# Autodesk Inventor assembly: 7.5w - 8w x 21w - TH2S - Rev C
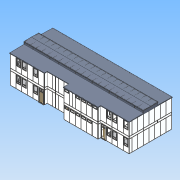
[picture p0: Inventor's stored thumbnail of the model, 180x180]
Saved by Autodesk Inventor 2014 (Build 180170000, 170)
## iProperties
Created: 2013-05
Part Number: 7.5w - 8w x 21w - TH2S - Rev C
Document SubType Name: Assembly
Designer: david.appleford
Mass: 5.25812e+07 g
Surface Area: 6.12104e+07 cm^2
Volume: 1.47344e+08 cm^3
Density: 0.356859 g/cm^3
Description: Coppice School Building
Justset: False
Title: Coppice School Building
Author: david.appleford
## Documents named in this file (76)
- C:\Documents and Settings\john.everitt\Local Settings\My Documents\Vault\Production MkII\4.00 BUILDINGS\Chigwell School\7.5w - 8w x 21w - TH2S - Rev C.iam
- C:\Documents and Settings\john.everitt\Local Settings\My Documents\Vault\Production MkII\VIRTUAL ELEMENTS\Virtual Walls\Virtual Timber + MgO\P0410S01K7L7-V.iam
- C:\Documents and Settings\john.everitt\Local Settings\My Documents\Vault\Production MkII\VIRTUAL ELEMENTS\Virtual Walls\Virtual Timber + MgO\P0409S01K7L6.5-V.iam
- C:\Documents and Settings\john.everitt\Local Settings\My Documents\Vault\Production MkII\VIRTUAL ELEMENTS\Virtual Walls\Virtual Timber + MgO\P0412S01K8L8-V.iam
- C:\Documents and Settings\john.everitt\Local Settings\My Documents\Vault\Production MkII\VIRTUAL ELEMENTS\Virtual Walls\Virtual Timber + MgO\P0408S01K6L6-V.iam
- C:\Documents and Settings\john.everitt\Local Settings\My Documents\Vault\Production MkII\VIRTUAL ELEMENTS\Virtual Walls\Virtual Timber + MgO\P0208S01K5L5-V.iam
- C:\Documents and Settings\john.everitt\Local Settings\My Documents\Vault\Production MkII\VIRTUAL ELEMENTS\Virtual Walls\Virtual Timber + MgO\P0204S01K3L3-V.iam
- C:\Documents and Settings\john.everitt\Local Settings\My Documents\Vault\Production MkII\VIRTUAL ELEMENTS\Virtual Walls\Virtual Timber + MgO\P0209S01K7L5.5L-V.iam
- C:\Documents and Settings\john.everitt\Local Settings\My Documents\Vault\Production MkII\VIRTUAL ELEMENTS\Virtual Walls\Virtual Timber + MgO\P0209S01K7L5.5R-V.iam
- C:\Documents and Settings\john.everitt\Local Settings\My Documents\Vault\Production MkII\VIRTUAL ELEMENTS\Virtual Walls\Virtual Timber + MgO\P0409S01K7L4.5-V.iam
- C:\Documents and Settings\john.everitt\Local Settings\My Documents\Vault\Production MkII\VIRTUAL ELEMENTS\Virtual Walls\Virtual Timber + MgO\P0409S01K7L2.5-V.iam
- C:\Documents and Settings\john.everitt\Local Settings\My Documents\Vault\Production MkII\VIRTUAL ELEMENTS\Virtual Walls\Virtual Timber + MgO\P0409S01K7L2-V.iam
- C:\Documents and Settings\john.everitt\Local Settings\My Documents\Vault\Production MkII\VIRTUAL ELEMENTS\Virtual Walls\Virtual Timber + MgO\P0209S01K7L4.5-V.iam
- C:\Documents and Settings\john.everitt\Local Settings\My Documents\Vault\Production MkII\VIRTUAL ELEMENTS\Virtual Walls\Virtual Timber + MgO\P0209S01K7L2.5-V.iam
- C:\Documents and Settings\john.everitt\Local Settings\My Documents\Vault\Production MkII\Virtual Elements\Virtual Walls\Virtual Timber + MgO\P0409S01K7-V.ipt
- C:\Documents and Settings\john.everitt\Local Settings\My Documents\Vault\Production MkII\4.00 BUILDINGS\Chigwell School\Stairs RH - U18R - 2.25w + 400mm Joist .ipt
- C:\Documents and Settings\john.everitt\Local Settings\My Documents\Vault\Production MkII\VIRTUAL ELEMENTS\Virtual Walls\Virtual Timber + MgO\P0406S01K5L2-V.iam
- C:\Documents and Settings\john.everitt\Local Settings\My Documents\Vault\Production MkII\VIRTUAL ELEMENTS\Virtual Ceilings\Ceiling MgO & Timber Frame\P0410C02K7L7-V.iam
- C:\Documents and Settings\john.everitt\Local Settings\My Documents\Vault\Production MkII\VIRTUAL ELEMENTS\Virtual Ceilings\Ceiling MgO & Timber Frame\P0412C02K8L8-V.iam
- C:\Documents and Settings\john.everitt\Local Settings\My Documents\Vault\Production MkII\VIRTUAL ELEMENTS\Virtual Ceilings\Ceiling MgO & Timber Frame\P0408C02K6L6-V.iam
- C:\Documents and Settings\john.everitt\Local Settings\My Documents\Vault\Production MkII\VIRTUAL ELEMENTS\Virtual Ceilings\Ceiling MgO & Timber Frame\P0204C02K3L3-V.iam
- C:\Documents and Settings\john.everitt\Local Settings\My Documents\Vault\Production MkII\VIRTUAL ELEMENTS\Virtual Joists\J16H397K18-T-V.ipt
- C:\Documents and Settings\john.everitt\Local Settings\My Documents\Vault\Production MkII\Virtual Elements\Virtual Joists\J14H400K16-T-V.ipt
- C:\Documents and Settings\john.everitt\Local Settings\My Documents\Vault\Production MkII\VIRTUAL ELEMENTS\Virtual Joists\J20H397K22-T-V.ipt
- C:\Documents and Settings\john.everitt\Local Settings\My Documents\Vault\Production MkII\Virtual Elements\Virtual Joists\J12S400K14-V.ipt
- C:\Documents and Settings\john.everitt\Local Settings\My Documents\Vault\Production MkII\Virtual Elements\Virtual Joists\J10S400K12-V.ipt
- C:\Documents and Settings\john.everitt\Local Settings\My Documents\Vault\Production MkII\Virtual Elements\Virtual Joists\J08S400K14-V.ipt
- C:\Documents and Settings\john.everitt\Local Settings\My Documents\Vault\Production MkII\VIRTUAL ELEMENTS\Virtual Joists\J04S397K5-V.ipt
- C:\Documents and Settings\john.everitt\Local Settings\My Documents\Vault\Production MkII\VIRTUAL ELEMENTS\Virtual Joists\J06S400K08-V.ipt
- C:\Documents and Settings\john.everitt\Local Settings\My Documents\Vault\Production MkII\Virtual Elements\Virtual Joists\J02S400K4-V.ipt
- C:\Documents and Settings\john.everitt\Local Settings\My Documents\Vault\Production MkII\VIRTUAL ELEMENTS\Virtual Lugs\Superceded Lugs\L400J3-V.ipt
- C:\Documents and Settings\john.everitt\Local Settings\My Documents\Vault\Production MkII\VIRTUAL ELEMENTS\Virtual Walls\Virtual Timber + MgO\P0409S01K7L5.5T-V.iam
- C:\Documents and Settings\john.everitt\Local Settings\My Documents\Vault\Production MkII\VIRTUAL ELEMENTS\Virtual Walls\Virtual Timber + MgO\P0409S01K7L3T-V.iam
- C:\Documents and Settings\john.everitt\Local Settings\My Documents\Vault\Production MkII\VIRTUAL ELEMENTS\Virtual Walls\Virtual Timber + MgO\P0409S01K7L3.5T-V.iam
- C:\Documents and Settings\john.everitt\Local Settings\My Documents\Vault\Production MkII\VIRTUAL ELEMENTS\Virtual Lugs\Superceded Lugs\LA02C3V.ipt
- C:\Documents and Settings\john.everitt\Local Settings\My Documents\Vault\Production MkII\VIRTUAL ELEMENTS\Virtual Lugs\Superceded Lugs\LA02M3V.ipt
- C:\Documents and Settings\john.everitt\Local Settings\My Documents\Vault\Production MkII\Virtual Elements\Virtual Walls\Virtual Timber + MgO\P0404S01K4L4-V.iam
- C:\Documents and Settings\john.everitt\Local Settings\My Documents\Vault\Production MkII\VIRTUAL ELEMENTS\Virtual Ceilings\Ceiling MgO & Timber Frame\P0212C02K8L7-V.iam
- C:\Documents and Settings\john.everitt\Local Settings\My Documents\Vault\Production MkII\VIRTUAL ELEMENTS\Virtual Ceilings\Ceiling MgO & Timber Frame\P0208C02K5L5-V.iam
- C:\Documents and Settings\john.everitt\Local Settings\My Documents\Vault\Production MkII\VIRTUAL ELEMENTS\Virtual Walls\Virtual Timber + MgO\P0404S01K4L1-V.iam
- C:\Documents and Settings\john.everitt\Local Settings\My Documents\Vault\Production MkII\VIRTUAL ELEMENTS\Virtual Walls\Virtual Timber + MgO\P0212S01K8L7-V.iam
- C:\Documents and Settings\john.everitt\Local Settings\My Documents\Vault\Production MkII\VIRTUAL ELEMENTS\Virtual Walls\Virtual Timber + MgO\P0206S01K5L4L-V.iam
- C:\Documents and Settings\john.everitt\Local Settings\My Documents\Vault\Production MkII\VIRTUAL ELEMENTS\Virtual Walls\Virtual Timber + MgO\P0206S01K5L4R-V.iam
- C:\Documents and Settings\john.everitt\Local Settings\My Documents\Vault\Production MkII\VIRTUAL ELEMENTS\Virtual Walls\Virtual Timber + MgO\P0212S01K8L4L-V.iam
- C:\Documents and Settings\john.everitt\Local Settings\My Documents\Vault\Production MkII\VIRTUAL ELEMENTS\Virtual Walls\Virtual Timber + MgO\P0210S01K7L5-V.iam
- C:\Documents and Settings\john.everitt\Local Settings\My Documents\Vault\Production MkII\VIRTUAL ELEMENTS\Virtual Walls\Virtual Timber + MgO\P0210S01K7L6L-V.iam
- C:\Documents and Settings\john.everitt\Local Settings\My Documents\Vault\Production MkII\VIRTUAL ELEMENTS\Virtual Walls\Virtual Timber + MgO\P0210S01K7L6R-V.iam
- C:\Documents and Settings\john.everitt\Local Settings\My Documents\Vault\Production MkII\Virtual Elements\Virtual Beams\B12R78X56K6E56TV.ipt
- C:\Documents and Settings\john.everitt\Local Settings\My Documents\Vault\Production MkII\VIRTUAL ELEMENTS\Virtual Beams\B10R78X56K5E56TV.ipt
- C:\Documents and Settings\john.everitt\Local Settings\My Documents\Vault\Production MkII\Virtual Elements\Virtual Beams\B12R78X56K6T-V.ipt
- C:\Documents and Settings\john.everitt\Local Settings\My Documents\Vault\Production MkII\Virtual Elements\Virtual Beams\B10R78X56K5T-V.ipt
- C:\Documents and Settings\john.everitt\Local Settings\My Documents\Vault\Production MkII\Virtual Elements\Virtual Beams\B08R78X56K4V.ipt
- C:\Documents and Settings\john.everitt\Local Settings\My Documents\Vault\Production MkII\VIRTUAL ELEMENTS\Virtual Beams\B08R78X56K4-T-V.ipt
- C:\Documents and Settings\john.everitt\Local Settings\My Documents\Vault\Production MkII\VIRTUAL ELEMENTS\Virtual Beams\B04R78X56K2V.ipt
- C:\Documents and Settings\john.everitt\Local Settings\My Documents\Vault\Production MkII\VIRTUAL ELEMENTS\Virtual Beams\B02R78X56K1-56-V.ipt
- C:\Documents and Settings\john.everitt\Local Settings\My Documents\Vault\Production MkII\VIRTUAL ELEMENTS\Virtual Roofs\Roof Wedges\X700W05D1V.ipt
- C:\Documents and Settings\john.everitt\Local Settings\My Documents\Vault\Production MkII\VIRTUAL ELEMENTS\Virtual Roofs\Roof Wedges\X700W05D2V.ipt
- C:\Documents and Settings\john.everitt\Local Settings\My Documents\Vault\Production MkII\Virtual Elements\Virtual Roofs\Roof Wedges\X700W06D1-V.ipt
- C:\Documents and Settings\john.everitt\Local Settings\My Documents\Vault\Production MkII\Virtual Elements\Virtual Walls\Virtual Timber + MgO\P0409W01F10T96K7L6.5-V.iam
- C:\Documents and Settings\john.everitt\Local Settings\My Documents\Vault\Production MkII\Virtual Elements\Virtual Walls\Virtual Timber + MgO\P0409W01F02T96K7L6.5-V.iam
- C:\Documents and Settings\john.everitt\Local Settings\My Documents\Vault\Production MkII\Virtual Elements\Virtual Walls\Virtual Timber + MgO\P0409DW01J01F02K6L5.5T-V.iam
- C:\Documents and Settings\john.everitt\Local Settings\My Documents\Vault\Production MkII\VIRTUAL ELEMENTS\Virtual Walls\Virtual Timber + MgO\P0409D01J01K7L5.5-V.iam
- C:\Documents and Settings\john.everitt\Local Settings\My Documents\Vault\Production MkII\Virtual Elements\Virtual Walls\Virtual Timber + MgO\P0409D01J01K6L4.5-V.iam
- C:\Documents and Settings\john.everitt\Local Settings\My Documents\Vault\Production MkII\Virtual Elements\Virtual Walls\Virtual Timber + MgO\P0409D01J01K6L2-V.iam
- C:\Documents and Settings\john.everitt\Local Settings\My Documents\Vault\Production MkII\VIRTUAL ELEMENTS\Virtual Windows\W1F10F1V1T-V.ipt
- C:\Documents and Settings\john.everitt\Local Settings\My Documents\Vault\Production MkII\Virtual Elements\Virtual Windows\W1F02V1-V.ipt
- C:\Documents and Settings\john.everitt\Local Settings\My Documents\Vault\Production MkII\VIRTUAL ELEMENTS\Virtual Doors\Star Projects\D1J01C9S44EL-V.iam
- C:\Documents and Settings\john.everitt\Local Settings\My Documents\Vault\Production MkII\VIRTUAL ELEMENTS\Virtual Doors\Star Projects\D1J01C9S44ER-V.iam
- C:\Documents and Settings\john.everitt\Local Settings\My Documents\Vault\Production MkII\Virtual Elements\Virtual Walls\Virtual Timber + MgO\P0409D01J01K6L2.5-V.iam
- C:\Documents and Settings\john.everitt\Local Settings\My Documents\Vault\Production MkII\VIRTUAL ELEMENTS\Virtual Doors\Door Furniture\T04TK1L1V.iam
- C:\Documents and Settings\john.everitt\Local Settings\My Documents\Vault\Production MkII\4.00 BUILDINGS\Chigwell School\External Facade 7.5w x 21w.ipt
- C:\Documents and Settings\john.everitt\Local Settings\My Documents\Vault\Production MkII\4.00 BUILDINGS\Chigwell School\EPDM 7.5w x 21w Cover.ipt
- C:\Documents and Settings\john.everitt\Local Settings\My Documents\Vault\Production MkII\VIRTUAL ELEMENTS\Virtual Ceilings\Ceiling MgO & Timber Frame\P0404C02K4L4-V.iam
- C:\Documents and Settings\john.everitt\Local Settings\My Documents\Vault\Production MkII\VIRTUAL ELEMENTS\Virtual Furniture\Table 1200mmSq School .ipt
- C:\Documents and Settings\john.everitt\Local Settings\My Documents\Vault\Production MkII\VIRTUAL ELEMENTS\Virtual Furniture\Chair 400mmSq School .ipt
- C:\Documents and Settings\john.everitt\Local Settings\My Documents\Vault\Production MkII\VIRTUAL ELEMENTS\Virtual Furniture\Table 1500 x 600 School .ipt
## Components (927 placed, 75 different names)
1. External Facade 7.5w x 21w:1
2. P0410S01K7L7-V:3 [sub-assembly]
3. P0410S01K7L7-V:6 [sub-assembly]
4. P0410S01K7L7-V:9 [sub-assembly]
5. P0410S01K7L7-V:12 [sub-assembly]
6. P0410S01K7L7-V:15 [sub-assembly]
7. P0410S01K7L7-V:18 [sub-assembly]
8. P0410S01K7L7-V:16 [sub-assembly]
9. P0410S01K7L7-V:13 [sub-assembly]
10. P0410S01K7L7-V:10 [sub-assembly]
11. P0410S01K7L7-V:7 [sub-assembly]
12. P0410S01K7L7-V:4 [sub-assembly]
13. P0410S01K7L7-V:1 [sub-assembly] — Mate:63, Mate:65
14. P0410S01K7L7-V:2 [sub-assembly] — Mate:41, Mate:42
15. P0410S01K7L7-V:5 [sub-assembly] — Mate:43, Mate:44, Mate:45
16. P0410S01K7L7-V:8 [sub-assembly]
17. P0410S01K7L7-V:11 [sub-assembly]
18. P0410S01K7L7-V:14 [sub-assembly]
19. P0410S01K7L7-V:17 [sub-assembly]
20. P0408S01K6L6-V:29 [sub-assembly] — Mate:26
21. P0412S01K8L8-V:29 [sub-assembly]
22. P0412S01K8L8-V:30 [sub-assembly]
23. P0408S01K6L6-V:3 [sub-assembly]
24. P0408S01K6L6-V:4 [sub-assembly]
25. P0412S01K8L8-V:4 [sub-assembly]
26. P0412S01K8L8-V:3 [sub-assembly]
27. P0408S01K6L6-V:28 [sub-assembly] — Mate:23
28. P0412S01K8L8-V:5 [sub-assembly]
29. P0408S01K6L6-V:5 [sub-assembly]
30. P0412S01K8L8-V:14 [sub-assembly]
31. P0412S01K8L8-V:13 [sub-assembly]
32. P0412S01K8L8-V:12 [sub-assembly]
33. P0408S01K6L6-V:7 [sub-assembly]
34. P0408S01K6L6-V:6 [sub-assembly]
35. P0412S01K8L8-V:6 [sub-assembly] — Mate:101
36. P0412S01K8L8-V:7 [sub-assembly] — Mate:102
37. P0412S01K8L8-V:8 [sub-assembly] — Mate:113, Mate:115
38. P0408S01K6L6-V:8 [sub-assembly]
39. P0412S01K8L8-V:11 [sub-assembly]
40. P0412S01K8L8-V:10 [sub-assembly] — Mate:109, Mate:117
41. P0408S01K6L6-V:9 [sub-assembly]
42. P0412S01K8L8-V:9 [sub-assembly]
43. P0410S01K7L7-V:19 [sub-assembly] — Mate:100
44. P0410S01K7L7-V:20 [sub-assembly]
45. P0410S01K7L7-V:21 [sub-assembly]
46. P0204S01K3L3-V:1 [sub-assembly]
47. P0410S01K7L7-V:22 [sub-assembly]
48. P0410S01K7L7-V:23 [sub-assembly]
49. P0410S01K7L7-V:24 [sub-assembly]
50. P0410S01K7L7-V:27 [sub-assembly]
51. P0410S01K7L7-V:26 [sub-assembly]
52. P0410S01K7L7-V:25 [sub-assembly]
53. P0410S01K7L7-V:28 [sub-assembly]
54. P0410S01K7L7-V:29 [sub-assembly]
55. P0410S01K7L7-V:30 [sub-assembly]
56. P0410S01K7L7-V:33 [sub-assembly]
57. P0410S01K7L7-V:32 [sub-assembly]
58. P0410S01K7L7-V:31 [sub-assembly]
59. P0410S01K7L7-V:36 [sub-assembly]
60. P0410S01K7L7-V:35 [sub-assembly] — Mate:104, Mate:105
61. P0410S01K7L7-V:34 [sub-assembly]
62. P0208S01K5L5-V:2 [sub-assembly]
63. P0408S01K6L6-V:10 [sub-assembly]
64. P0208S01K5L5-V:1 [sub-assembly]
65. P0408S01K6L6-V:12 [sub-assembly]
66. P0408S01K6L6-V:13 [sub-assembly]
67. P0409DW01J01F02K6L5.5T-V:8 [sub-assembly] — Mate:22, Mate:24
68. P0409DW01J01F02K6L5.5T-V:7 [sub-assembly] — Mate:25, Mate:27
69. P0409W01F02T96K7L6.5-V:7 [sub-assembly]
70. P0409W01F02T96K7L6.5-V:8 [sub-assembly]
71. P0409W01F02T96K7L6.5-V:9 [sub-assembly]
72. P0409W01F02T96K7L6.5-V:10 [sub-assembly]
73. P0409W01F02T96K7L6.5-V:11 [sub-assembly] — Mate:111
74. P0409S01K7L6.5-V:66 [sub-assembly]
75. P0409S01K7L6.5-V:57 [sub-assembly]
76. P0409S01K7L6.5-V:59 [sub-assembly]
77. P0409S01K7L6.5-V:60 [sub-assembly]
78. P0409S01K7L6.5-V:4 [sub-assembly]
79. P0409S01K7L6.5-V:1 [sub-assembly]
80. P0409S01K7L6.5-V:55 [sub-assembly]
81. P0409W01F10T96K7L6.5-V:7 [sub-assembly]
82. P0409W01F10T96K7L6.5-V:16 [sub-assembly]
83. P0409S01K7L6.5-V:54 [sub-assembly]
84. P0409W01F10T96K7L6.5-V:17 [sub-assembly]
85. P0409W01F10T96K7L6.5-V:8 [sub-assembly]
86. P0409S01K7L6.5-V:49 [sub-assembly]
87. P0409W01F10T96K7L6.5-V:9 [sub-assembly]
88. P0409W01F10T96K7L6.5-V:18 [sub-assembly]
89. P0409DW01J01F02K6L5.5T-V:1 [sub-assembly]
90. P0409DW01J01F02K6L5.5T-V:4 [sub-assembly]
91. P0409W01F02T96K7L6.5-V:12 [sub-assembly]
92. P0409W01F02T96K7L6.5-V:13 [sub-assembly]
93. P0409W01F02T96K7L6.5-V:14 [sub-assembly]
94. P0409W01F02T96K7L6.5-V:15 [sub-assembly]
95. P0409W01F02T96K7L6.5-V:16 [sub-assembly]
96. P0409W01F02T96K7L6.5-V:17 [sub-assembly]
97. P0409W01F02T96K7L6.5-V:18 [sub-assembly]
98. P0409S01K7L6.5-V:25 [sub-assembly]
99. P0409DW01J01F02K6L5.5T-V:2 [sub-assembly]
100. P0409W01F10T96K7L6.5-V:19 [sub-assembly]
101. P0409W01F10T96K7L6.5-V:3 [sub-assembly]
102. P0409S01K7L6.5-V:21 [sub-assembly]
103. P0409S01K7L6.5-V:22 [sub-assembly]
104. P0409W01F10T96K7L6.5-V:20 [sub-assembly]
105. P0409W01F10T96K7L6.5-V:2 [sub-assembly]
106. P0409W01F10T96K7L6.5-V:21 [sub-assembly]
107. P0409W01F10T96K7L6.5-V:1 [sub-assembly]
108. P0409S01K7L6.5-V:2 [sub-assembly]
109. P0409S01K7L6.5-V:3 [sub-assembly]
110. P0409S01K7L6.5-V:15 [sub-assembly]
111. P0409S01K7L6.5-V:16 [sub-assembly]
112. P0409S01K7L6.5-V:13 [sub-assembly]
113. P0409S01K7L6.5-V:14 [sub-assembly]
114. P0409S01K7L6.5-V:11 [sub-assembly]
115. P0409S01K7L6.5-V:12 [sub-assembly]
116. P0409S01K7L6.5-V:9 [sub-assembly] — Mate:107
117. P0409S01K7L6.5-V:10 [sub-assembly]
118. P0409S01K7L6.5-V:7 [sub-assembly]
119. P0409S01K7L6.5-V:8 [sub-assembly] — Mate:64
120. P0409S01K7L6.5-V:5 [sub-assembly]
121. P0409S01K7L6.5-V:6 [sub-assembly]
122. P0209S01K7L5.5L-V:3 [sub-assembly]
123. P0209S01K7L5.5R-V:3 [sub-assembly]
124. P0409DW01J01F02K6L5.5T-V:3 [sub-assembly]
125. P0209S01K7L5.5L-V:2 [sub-assembly]
126. P0209S01K7L5.5R-V:2 [sub-assembly]
127. P0209S01K7L5.5L-V:1 [sub-assembly]
128. P0209S01K7L5.5R-V:1 [sub-assembly]
129. W1F02V1-V:12
130. W1F02V1-V:11
131. W1F02V1-V:14
132. W1F02V1-V:20
133. W1F02V1-V:19
134. W1F02V1-V:18
135. W1F02V1-V:17
136. W1F02V1-V:16
137. W1F02V1-V:15
138. W1F02V1-V:13
139. W1F10F1V1T-V:23
140. W1F10F1V1T-V:21
141. W1F10F1V1T-V:2
142. W1F10F1V1T-V:53
143. W1F10F1V1T-V:52
144. W1F10F1V1T-V:50
145. W1F10F1V1T-V:46
146. W1F10F1V1T-V:45
147. W1F10F1V1T-V:43
148. W1F10F1V1T-V:38
149. W1F10F1V1T-V:37
150. W1F10F1V1T-V:35
151. W1F02V1-V:10
152. W1F02V1-V:9
153. W1F02V1-V:8
154. W1F02V1-V:7
155. W1F02V1-V:6
156. W1F02V1-V:5
157. W1F02V1-V:4
158. W1F02V1-V:3
159. P0409D01J01K6L2.5-V:2 [sub-assembly]
160. P0409D01J01K6L2-V:2 [sub-assembly]
161. P0409S01K7L4.5-V:47 [sub-assembly]
162. P0409S01K7L4.5-V:48 [sub-assembly]
163. P0409S01K7L4.5-V:46 [sub-assembly]
164. P0409S01K7L4.5-V:9 [sub-assembly]
165. P0409S01K7L2-V:13 [sub-assembly]
166. P0409S01K7L2.5-V:9 [sub-assembly]
167. P0209S01K7L4.5-V:3 [sub-assembly]
168. P0409D01J01K6L2.5-V:1 [sub-assembly]
169. P0409S01K7L5.5T-V:1 [sub-assembly]
170. P0409S01K7L3T-V:1 [sub-assembly]
171. P0409S01K7L4.5-V:11 [sub-assembly]
172. P0409S01K7L4.5-V:8 [sub-assembly]
173. P0409S01K7L2-V:2 [sub-assembly] — Mate:9
174. P0409D01J01K6L4.5-V:5 [sub-assembly]
175. P0409S01K7L4.5-V:5 [sub-assembly]
176. P0409S01K7L4.5-V:6 [sub-assembly]
177. P0409S01K7L2-V:1 [sub-assembly]
178. P0409S01K7L4.5-V:3 [sub-assembly]
179. P0209S01K7L4.5-V:2 [sub-assembly]
180. P0209S01K7L2.5-V:1 [sub-assembly] — Mate:112
181. P0409S01K7-V:1
182. P0409S01K7L4.5-V:12 [sub-assembly]
183. P0409S01K7L4.5-V:13 [sub-assembly]
184. P0406S01K5L2-V:1 [sub-assembly]
185. P0409S01K7L5.5T-V:2 [sub-assembly]
186. P0409S01K7L4.5-V:20 [sub-assembly]
187. P0409D01J01K6L4.5-V:4 [sub-assembly]
188. P0409S01K7L4.5-V:22 [sub-assembly]
189. P0409S01K7L4.5-V:24 [sub-assembly]
190. D1J01C9S44ER-V:17 [sub-assembly]
191. D1J01C9S44EL-V:7 [sub-assembly]
192. D1J01C9S44EL-V:3 [sub-assembly] — Mate:22, Mate:23, Mate:24
193. D1J01C9S44ER-V:5 [sub-assembly] — Mate:25, Mate:26, Mate:27
194. T04TK1L1V:2 [sub-assembly]
195. T04TK1L1V:3 [sub-assembly]
196. T04TK1L1V:4 [sub-assembly]
197. T04TK1L1V:5 [sub-assembly]
198. T04TK1L1V:6 [sub-assembly]
199. T04TK1L1V:1 [sub-assembly]
200. D1J01C9S44ER-V:6 [sub-assembly]
201. D1J01C9S44EL-V:5 [sub-assembly]
202. D1J01C9S44EL-V:6 [sub-assembly]
203. D1J01C9S44ER-V:3 [sub-assembly]
204. D1J01C9S44EL-V:2 [sub-assembly]
205. D1J01C9S44ER-V:4 [sub-assembly]
206. D1J01C9S44ER-V:2 [sub-assembly]
207. P0408C02K6L6-V:18 [sub-assembly]
208. P0408C02K6L6-V:19 [sub-assembly]
209. P0410C02K7L7-V:23 [sub-assembly]
210. P0410C02K7L7-V:57 [sub-assembly]
211. P0410C02K7L7-V:35 [sub-assembly]
212. P0410C02K7L7-V:34 [sub-assembly]
213. P0410C02K7L7-V:56 [sub-assembly]
214. P0410C02K7L7-V:22 [sub-assembly]
215. P0410C02K7L7-V:21 [sub-assembly]
216. P0410C02K7L7-V:55 [sub-assembly]
217. P0410C02K7L7-V:33 [sub-assembly]
218. P0410C02K7L7-V:32 [sub-assembly]
219. P0410C02K7L7-V:54 [sub-assembly]
220. P0410C02K7L7-V:20 [sub-assembly]
221. P0410C02K7L7-V:19 [sub-assembly]
222. P0410C02K7L7-V:53 [sub-assembly]
223. P0410C02K7L7-V:31 [sub-assembly]
224. P0204C02K3L3-V:1 [sub-assembly]
225. P0410C02K7L7-V:30 [sub-assembly]
226. P0410C02K7L7-V:52 [sub-assembly]
227. P0410C02K7L7-V:36 [sub-assembly]
228. P0412C02K8L8-V:17 [sub-assembly]
229. P0412C02K8L8-V:15 [sub-assembly]
230. P0412C02K8L8-V:13 [sub-assembly]
231. P0412C02K8L8-V:11 [sub-assembly]
232. P0412C02K8L8-V:9 [sub-assembly]
233. P0412C02K8L8-V:7 [sub-assembly]
234. P0412C02K8L8-V:5 [sub-assembly]
235. P0410C02K7L7-V:6 [sub-assembly]
236. P0410C02K7L7-V:5 [sub-assembly]
237. P0410C02K7L7-V:4 [sub-assembly]
238. P0410C02K7L7-V:3 [sub-assembly]
239. P0410C02K7L7-V:2 [sub-assembly]
240. P0410C02K7L7-V:1 [sub-assembly]
241. P0410C02K7L7-V:37 [sub-assembly]
242. P0410C02K7L7-V:38 [sub-assembly]
243. P0410C02K7L7-V:39 [sub-assembly]
244. P0410C02K7L7-V:40 [sub-assembly]
245. P0410C02K7L7-V:41 [sub-assembly]
246. P0410C02K7L7-V:42 [sub-assembly]
247. P0410C02K7L7-V:18 [sub-assembly]
248. P0410C02K7L7-V:17 [sub-assembly]
249. P0410C02K7L7-V:16 [sub-assembly]
250. P0410C02K7L7-V:15 [sub-assembly]
251. P0410C02K7L7-V:14 [sub-assembly]
252. P0410C02K7L7-V:13 [sub-assembly]
253. P0412C02K8L8-V:10 [sub-assembly]
254. P0412C02K8L8-V:12 [sub-assembly]
255. P0412C02K8L8-V:14 [sub-assembly]
256. P0412C02K8L8-V:16 [sub-assembly]
257. P0412C02K8L8-V:18 [sub-assembly]
258. P0412S01K8L8-V:32 [sub-assembly]
259. P0408C02K6L6-V:3 [sub-assembly]
260. P0408C02K6L6-V:4 [sub-assembly]
261. P0408C02K6L6-V:5 [sub-assembly]
262. P0408C02K6L6-V:6 [sub-assembly]
263. P0408C02K6L6-V:7 [sub-assembly]
264. P0408C02K6L6-V:8 [sub-assembly]
265. P0408C02K6L6-V:9 [sub-assembly]
266. P0412S01K8L8-V:31 [sub-assembly]
267. J16H397K18-T-V:23
268. J16H397K18-T-V:22
269. J16H397K18-T-V:13
270. J20H397K22-T-V:8
271. J20H397K22-T-V:1
272. J16H397K18-T-V:24
273. J16H397K18-T-V:4
274. Stairs RH - U18R - 2.25w + 400mm Joist :1
275. L400J3-V:18
276. L400J3-V:54
277. L400J3-V:53
278. L400J3-V:23
279. L400J3-V:56
280. L400J3-V:55
281. LA02C3V:3
282. LA02C3V:4
283. LA02C3V:5
284. LA02C3V:11
285. LA02M3V:1
286. LA02C3V:1
287. LA02C3V:13
288. LA02C3V:12
289. LA02C3V:10
290. LA02C3V:8
291. LA02C3V:14
292. LA02C3V:15
293. LA02C3V:16
294. LA02C3V:2
295. LA02M3V:2
296. P0208S01K5L5-V:4 [sub-assembly] — Mate:37, Mate:38, Flush:18
297. P0404S01K4L4-V:10 [sub-assembly]
298. P0408S01K6L6-V:27 [sub-assembly]
299. P0208S01K5L5-V:3 [sub-assembly] — Mate:36, Mate:38, Flush:18
300. P0404S01K4L4-V:9 [sub-assembly] — Mate:37
301. P0404S01K4L4-V:8 [sub-assembly]
302. P0408S01K6L6-V:25 [sub-assembly]
303. P0404S01K4L4-V:2 [sub-assembly]
304. P0408S01K6L6-V:24 [sub-assembly]
305. P0404S01K4L4-V:3 [sub-assembly]
306. P0404S01K4L4-V:5 [sub-assembly]
307. P0404S01K4L4-V:7 [sub-assembly]
308. P0408S01K6L6-V:23 [sub-assembly]
309. P0404S01K4L4-V:1 [sub-assembly]
310. P0410S01K7L7-V:72 [sub-assembly]
311. P0410S01K7L7-V:71 [sub-assembly]
312. P0410S01K7L7-V:70 [sub-assembly]
313. P0410S01K7L7-V:69 [sub-assembly]
314. P0410S01K7L7-V:68 [sub-assembly]
315. P0410S01K7L7-V:67 [sub-assembly]
316. P0410S01K7L7-V:66 [sub-assembly]
317. P0410S01K7L7-V:65 [sub-assembly]
318. P0410S01K7L7-V:64 [sub-assembly]
319. P0410S01K7L7-V:63 [sub-assembly]
320. P0410S01K7L7-V:62 [sub-assembly]
321. P0410S01K7L7-V:61 [sub-assembly]
322. P0410S01K7L7-V:60 [sub-assembly]
323. P0410S01K7L7-V:59 [sub-assembly]
324. P0410S01K7L7-V:58 [sub-assembly]
325. P0410S01K7L7-V:56 [sub-assembly]
326. P0410S01K7L7-V:55 [sub-assembly] — Mate:19
327. P0412S01K8L8-V:28 [sub-assembly]
328. P0408S01K6L6-V:22 [sub-assembly]
329. P0408S01K6L6-V:21 [sub-assembly]
330. P0412S01K8L8-V:25 [sub-assembly]
331. P0412S01K8L8-V:24 [sub-assembly]
332. P0412S01K8L8-V:23 [sub-assembly]
333. P0408S01K6L6-V:20 [sub-assembly]
334. P0408S01K6L6-V:19 [sub-assembly]
335. P0408S01K6L6-V:18 [sub-assembly]
336. P0412S01K8L8-V:33 [sub-assembly] — Flush:12
337. P0412S01K8L8-V:18 [sub-assembly] — Mate:83
338. P0412S01K8L8-V:17 [sub-assembly]
339. P0412S01K8L8-V:16 [sub-assembly]
340. P0408S01K6L6-V:17 [sub-assembly]
341. P0408S01K6L6-V:16 [sub-assembly]
342. P0408S01K6L6-V:15 [sub-assembly]
343. P0408S01K6L6-V:14 [sub-assembly]
344. P0412S01K8L8-V:15 [sub-assembly]
345. P0410S01K7L7-V:54 [sub-assembly] — Mate:82
346. P0410S01K7L7-V:53 [sub-assembly]
347. P0410S01K7L7-V:52 [sub-assembly]
348. P0410S01K7L7-V:51 [sub-assembly]
349. P0410S01K7L7-V:50 [sub-assembly]
350. P0410S01K7L7-V:49 [sub-assembly]
351. P0410S01K7L7-V:48 [sub-assembly] — Mate:72
352. P0410S01K7L7-V:47 [sub-assembly]
353. P0410S01K7L7-V:46 [sub-assembly]
354. P0410S01K7L7-V:45 [sub-assembly]
355. P0410S01K7L7-V:44 [sub-assembly]
356. P0410S01K7L7-V:43 [sub-assembly]
357. P0410S01K7L7-V:42 [sub-assembly]
358. P0410S01K7L7-V:41 [sub-assembly]
359. P0410S01K7L7-V:40 [sub-assembly]
360. P0410S01K7L7-V:39 [sub-assembly]
361. P0410S01K7L7-V:38 [sub-assembly]
362. P0410S01K7L7-V:37 [sub-assembly]
363. P0209S01K7L5.5R-V:7 [sub-assembly] — Mate:35, Mate:36, Flush:17
364. P0409S01K7L6.5-V:120 [sub-assembly]
365. P0409S01K7L6.5-V:101 [sub-assembly]
366. P0409S01K7L6.5-V:121 [sub-assembly]
367. P0409S01K7L6.5-V:93 [sub-assembly]
368. P0409W01F02T96K7L6.5-V:1 [sub-assembly] — Mate:35, Flush:17
369. P0209S01K7L5.5L-V:7 [sub-assembly]
370. P0409W01F02T96K7L6.5-V:3 [sub-assembly]
371. P0409W01F02T96K7L6.5-V:4 [sub-assembly]
372. P0409W01F02T96K7L6.5-V:5 [sub-assembly]
373. P0409W01F02T96K7L6.5-V:6 [sub-assembly]
374. P0409S01K7L6.5-V:117 [sub-assembly]
375. P0409S01K7L6.5-V:116 [sub-assembly]
376. P0409S01K7L6.5-V:115 [sub-assembly]
377. P0409S01K7L6.5-V:114 [sub-assembly]
378. P0409S01K7L6.5-V:113 [sub-assembly]
379. P0409S01K7L6.5-V:112 [sub-assembly]
380. P0409W01F10T96K7L6.5-V:12 [sub-assembly]
381. P0409W01F10T96K7L6.5-V:13 [sub-assembly]
382. P0409S01K7L6.5-V:109 [sub-assembly]
383. P0409W01F10T96K7L6.5-V:14 [sub-assembly]
384. P0409W01F10T96K7L6.5-V:11 [sub-assembly]
385. P0409S01K7L6.5-V:106 [sub-assembly]
386. P0409W01F10T96K7L6.5-V:10 [sub-assembly]
387. P0409W01F10T96K7L6.5-V:15 [sub-assembly]
388. P0409S01K7L6.5-V:103 [sub-assembly]
389. P0409W01F10T96K7L6.5-V:28 [sub-assembly]
390. P0409W01F10T96K7L6.5-V:27 [sub-assembly]
391. P0409S01K7L6.5-V:98 [sub-assembly]
392. P0409W01F10T96K7L6.5-V:26 [sub-assembly] — Flush:12
393. P0409S01K7L6.5-V:96 [sub-assembly]
394. P0409S01K7L6.5-V:95 [sub-assembly]
395. P0409W01F10T96K7L6.5-V:25 [sub-assembly]
396. P0409S01K7L6.5-V:91 [sub-assembly]
397. P0409W01F10T96K7L6.5-V:22 [sub-assembly]
398. P0409W01F10T96K7L6.5-V:6 [sub-assembly]
399. P0409S01K7L6.5-V:88 [sub-assembly] — Flush:6
400. P0409S01K7L6.5-V:87 [sub-assembly]
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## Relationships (116: Mate 91, Flush 25)
- Mate:9: P0409S01K7L2-V:2 ↔ J04S397K5-V:9
- Flush:4: J04S397K5-V:9 ↔ J08S400K14-V:2
- Flush:6: P0409S01K7L6.5-V:88 ↔ J08S400K14-V:3
- Flush:12: P0412S01K8L8-V:33 ↔ P0409W01F10T96K7L6.5-V:26
- Mate:19: P0410S01K7L7-V:55 ↔ D1J01C9S44ER-V:14
- Mate:20: P0409D01J01K6L4.5-V:7 ↔ D1J01C9S44ER-V:14
- Mate:21: P0409D01J01K6L4.5-V:7 ↔ D1J01C9S44ER-V:14
- Mate:22: P0409DW01J01F02K6L5.5T-V:8 ↔ D1J01C9S44EL-V:3
- Mate:23: P0408S01K6L6-V:28 ↔ D1J01C9S44EL-V:3
- Mate:24: P0409DW01J01F02K6L5.5T-V:8 ↔ D1J01C9S44EL-V:3
- Mate:25: P0409DW01J01F02K6L5.5T-V:7 ↔ D1J01C9S44ER-V:5
- Mate:26: P0408S01K6L6-V:29 ↔ D1J01C9S44ER-V:5
- Mate:27: P0409DW01J01F02K6L5.5T-V:7 ↔ D1J01C9S44ER-V:5
- Mate:28: P0409D01J01K7L5.5-V:2 ↔ P0204S01K3L3-V:2
- Mate:29: P0204S01K3L3-V:2 ↔ P0212C02K8L7-V:1
- Flush:15: P0409D01J01K7L5.5-V:2 ↔ P0204S01K3L3-V:2
- Mate:31: P0208C02K5L5-V:3 ↔ P0204S01K3L3-V:2
- Mate:33: P0204S01K3L3-V:3 ↔ P0408C02K6L6-V:10
- Mate:34: P0204S01K3L3-V:3 ↔ P0410C02K7L7-V:97
- Mate:35: P0209S01K7L5.5R-V:7 ↔ P0409W01F02T96K7L6.5-V:1
- Mate:36: P0208S01K5L5-V:3 ↔ P0209S01K7L5.5R-V:7
- Flush:17: P0209S01K7L5.5R-V:7 ↔ P0409W01F02T96K7L6.5-V:1
- Mate:37: P0208S01K5L5-V:4 ↔ P0404S01K4L4-V:9
- Mate:38: P0208S01K5L5-V:4 ↔ P0208S01K5L5-V:3
- Flush:18: P0208S01K5L5-V:4 ↔ P0208S01K5L5-V:3
- Mate:39: P0208C02K5L5-V:5 ↔ P0404C02K4L4-V:7
- Mate:40: P0208C02K5L5-V:5 ↔ P0208C02K5L5-V:4
- Flush:19: P0208C02K5L5-V:5 ↔ P0404C02K4L4-V:7
- Mate:41: P0410S01K7L7-V:2 ↔ Chair 400mmSq School :1
- Mate:42: P0410S01K7L7-V:2 ↔ Table 1200mmSq School :1
- Mate:43: P0410S01K7L7-V:5 ↔ Chair 400mmSq School :4
- Mate:44: P0410S01K7L7-V:5 ↔ Chair 400mmSq School :3
- Mate:45: P0410S01K7L7-V:5 ↔ Chair 400mmSq School :2
- Mate:46: Table 1200mmSq School :1 ↔ Chair 400mmSq School :4
- Mate:47: Table 1200mmSq School :1 ↔ Chair 400mmSq School :3
- Mate:48: Table 1200mmSq School :1 ↔ Chair 400mmSq School :2
- Mate:49: Table 1200mmSq School :1 ↔ Chair 400mmSq School :1
- Mate:50: Table 1200mmSq School :1 ↔ Chair 400mmSq School :3
- Mate:51: Table 1200mmSq School :1 ↔ Chair 400mmSq School :4
- Mate:52: Table 1200mmSq School :1 ↔ Chair 400mmSq School :1
- Mate:53: Table 1200mmSq School :1 ↔ Chair 400mmSq School :2
- Mate:63: P0410S01K7L7-V:1 ↔ Table 1500 x 600 School :1
- Mate:64: P0409S01K7L6.5-V:8 ↔ Table 1500 x 600 School :1
- Mate:65: P0410S01K7L7-V:1 ↔ Chair 400mmSq School :33
- Mate:66: Table 1500 x 600 School :1 ↔ Chair 400mmSq School :33
- Mate:67: Table 1500 x 600 School :1 ↔ Chair 400mmSq School :33
- Flush:26: Chair 400mmSq School :38 ↔ Table 1500 x 600 School :2
- Mate:70: Chair 400mmSq School :38 ↔ Table 1500 x 600 School :2
- Mate:71: Chair 400mmSq School :38 ↔ Table 1500 x 600 School :2
- Mate:72: P0410S01K7L7-V:48 ↔ Table 1500 x 600 School :2
- Mate:73: P0409S01K7L6.5-V:73 ↔ Table 1500 x 600 School :2
- Flush:27: Chair 400mmSq School :36 ↔ Table 1200mmSq School :9
- Mate:74: Chair 400mmSq School :36 ↔ Table 1200mmSq School :9
- Flush:28: Chair 400mmSq School :35 ↔ Table 1200mmSq School :9
- Mate:75: Chair 400mmSq School :35 ↔ Table 1200mmSq School :9
- Mate:76: Chair 400mmSq School :37 ↔ Table 1200mmSq School :9
- Flush:29: Chair 400mmSq School :37 ↔ Table 1200mmSq School :9
- Flush:30: Chair 400mmSq School :34 ↔ Table 1200mmSq School :9
- Mate:77: Chair 400mmSq School :34 ↔ Table 1200mmSq School :9
- Mate:78: Chair 400mmSq School :36 ↔ Table 1200mmSq School :9
- Mate:79: Chair 400mmSq School :34 ↔ Table 1200mmSq School :9
- Mate:80: Chair 400mmSq School :35 ↔ Table 1200mmSq School :9
- Mate:81: Chair 400mmSq School :37 ↔ Table 1200mmSq School :9
- Mate:82: P0410S01K7L7-V:54 ↔ Table 1200mmSq School :9
- Mate:83: P0412S01K8L8-V:18 ↔ Table 1200mmSq School :10
- Flush:31: Table 1200mmSq School :52 ↔ Chair 400mmSq School :191
- Flush:32: Table 1200mmSq School :52 ↔ Chair 400mmSq School :194
- Flush:33: Table 1200mmSq School :52 ↔ Chair 400mmSq School :192
- Flush:34: Table 1200mmSq School :52 ↔ Chair 400mmSq School :192
- Mate:84: Table 1200mmSq School :52 ↔ Chair 400mmSq School :191
- Mate:85: Table 1200mmSq School :52 ↔ Chair 400mmSq School :192
- Mate:86: Table 1200mmSq School :52 ↔ Chair 400mmSq School :193
- Mate:87: Table 1200mmSq School :52 ↔ Chair 400mmSq School :194
- Mate:88: Table 1200mmSq School :52 ↔ Chair 400mmSq School :191
- Mate:89: Table 1200mmSq School :52 ↔ Chair 400mmSq School :192
- Mate:90: Table 1200mmSq School :52 ↔ Chair 400mmSq School :193
- Mate:91: Table 1200mmSq School :52 ↔ Chair 400mmSq School :194
- Mate:92: Chair 400mmSq School :195 ↔ Table 1200mmSq School :53
- Mate:93: Chair 400mmSq School :196 ↔ Table 1200mmSq School :53
- Mate:94: Chair 400mmSq School :197 ↔ Table 1200mmSq School :53
- Mate:95: Chair 400mmSq School :198 ↔ Table 1200mmSq School :53
- Flush:35: Chair 400mmSq School :196 ↔ Table 1200mmSq School :53
- Flush:36: Chair 400mmSq School :195 ↔ Table 1200mmSq School :53
- Flush:37: Chair 400mmSq School :197 ↔ Table 1200mmSq School :53
- Flush:38: Chair 400mmSq School :198 ↔ Table 1200mmSq School :53
- Mate:96: Chair 400mmSq School :198 ↔ Table 1200mmSq School :53
- Mate:97: Chair 400mmSq School :195 ↔ Table 1200mmSq School :53
- Mate:98: Chair 400mmSq School :196 ↔ Table 1200mmSq School :53
- Mate:99: Chair 400mmSq School :197 ↔ Table 1200mmSq School :53
- Mate:100: P0410S01K7L7-V:19 ↔ Table 1200mmSq School :53
- Mate:101: P0412S01K8L8-V:6 ↔ Table 1200mmSq School :52
- Flush:39: Table 1200mmSq School :52 ↔ Chair 400mmSq School :193
- Mate:102: P0412S01K8L8-V:7 ↔ Table 1200mmSq School :52
- Mate:103: Table 1500 x 600 School :3 ↔ Chair 400mmSq School :199
- Mate:104: P0410S01K7L7-V:35 ↔ Chair 400mmSq School :199
- Mate:105: P0410S01K7L7-V:35 ↔ Table 1500 x 600 School :3
- Mate:106: Table 1500 x 600 School :3 ↔ Chair 400mmSq School :199
- Mate:107: P0409S01K7L6.5-V:9 ↔ Table 1500 x 600 School :3
- Flush:40: Table 1500 x 600 School :6 ↔ Table 1500 x 600 School :4
- Flush:41: Table 1500 x 600 School :5 ↔ Table 1500 x 600 School :4
- Flush:109: Table 1500 x 600 School :6 ↔ Table 1500 x 600 School :4
- Mate:122: Table 1500 x 600 School :6 ↔ Table 1500 x 600 School :4
- Mate:110: Table 1500 x 600 School :6 ↔ Table 1500 x 600 School :5
- Mate:109: P0412S01K8L8-V:10 ↔ Table 1500 x 600 School :4
- Mate:111: P0409W01F02T96K7L6.5-V:11 ↔ Table 1500 x 600 School :4
- Mate:112: P0209S01K7L2.5-V:1 ↔ Table 1500 x 600 School :6
- Flush:43: Table 1500 x 600 School :11 ↔ Table 1500 x 600 School :5
- Mate:113: P0412S01K8L8-V:8 ↔ Chair 400mmSq School :284
- Mate:114: Table 1500 x 600 School :5 ↔ Chair 400mmSq School :284
- Mate:115: P0412S01K8L8-V:8 ↔ Chair 400mmSq School :285
- Mate:116: Table 1500 x 600 School :11 ↔ Chair 400mmSq School :285
- Mate:117: P0412S01K8L8-V:10 ↔ Chair 400mmSq School :286
- Mate:118: Table 1500 x 600 School :4 ↔ Chair 400mmSq School :286
- Mate:119: Table 1500 x 600 School :4 ↔ Chair 400mmSq School :286
- Mate:120: Table 1500 x 600 School :11 ↔ Chair 400mmSq School :285
- Mate:121: Table 1500 x 600 School :5 ↔ Chair 400mmSq School :284
